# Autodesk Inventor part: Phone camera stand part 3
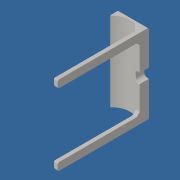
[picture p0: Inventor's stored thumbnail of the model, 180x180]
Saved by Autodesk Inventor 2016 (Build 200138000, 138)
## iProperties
Created: 2016-02
Part Number: Phone camera stand part 3
Material: Generic
Document SubType Name: Modeling
Designer: Miha
Density: 1 g/cm^3
Appearance: Default
Author: Miha
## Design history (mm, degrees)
sketch "Sketch1"
  geometry: L1 (0, 0)-(45, 0); L2 (0, 0)-(45, 0); L3 (45, 0)-(45, -20); L4 (45, 0)-(65, 0); L5 (45, 0)-(45, 20); L6 (45, 0)-(65, 0); L7 (45, -20)-(0, -20); L8 (0, -20)-(0, -24.8); L9 (0, -24.8)-(45, -24.8); L10 (45, -24.8)-(45, -20); L11 (45, 20)-(0, 20); L12 (0, 20)-(0, 24.8); L13 (0, 24.8)-(45, 24.8); L14 (45, 24.8)-(45, 20)
  constraints: 28 end point, 6 horizontal, 4 parallel, 3 equal length, 3 perpendicular, 1 vertical
  dimensions: "d20" = 45 distance of L1.start L1.end; "d21" = 0 distance between parallel lines of L1 L2 (derived); "d22" = 20 distance of L2.end L3.end; "d23" = 90 deg angle of L3 L4 (derived); "d24" = 20 distance of L2.end L5.end; "d25" = 90 deg angle of L6 L5 (derived); "d26" = 45 distance of L9.end L8.end; "d27" = 4.8 distance of L8.end L7.end; "d28" = 45 distance of L12.end L13.end; "d29" = 4.8 distance of L11.end L12.end
extrude "Extrusion1" new body sketch "Sketch1" distance "d30" = 3; taper "d31" = 0 deg
sketch "Sketch2"
  geometry: L1 (3, 4.8)-(3, 0) reference; L2 (3, 0)-(-7, 0); L3 (-7, 0)-(-7, 49.6); L4 (-7, 49.6)-(3, 49.6); L5 (3, 49.6)-(3, 0); 1 further point
  constraints: 8 end point, 2 parallel, 1 horizontal, 1 perpendicular
  dimensions: "d32" = 10 distance of L3.end L4.end; "d33" = 49.6 distance of L2.end L3.end
extrude "Extrusion2" join sketch "Sketch2" distance "d34" = 2; taper "d35" = 0 deg
sketch "Sketch3"
  geometry: L1 (49.6, 2)-(0, 2) reference; L2 (49.6, 0)-(0, 0) reference; L3 (0, 2)-(49.6, 2); L4 (49.6, 2)-(49.6, 0); L5 (49.6, 0)-(0, 0); L6 (0, 0)-(0, 2); 1 further point
  constraints: 8 end point, 2 parallel, 1 horizontal, 1 perpendicular
extrude "Extrusion3" join sketch "Sketch3" distance "d36" = 8.7; taper "d37" = 0 deg
chamfer "Chamfer1" distance "d38" = 3.7; stored, may be unused: second distance "d39" = 2, angle "d40" = 45 deg
sketch "Sketch4"
  geometry: L1 (-3.7, 45)-(0, 41.3) reference; L2 (3, 45)-(-3.7, 45) reference; L3 (-3.7, 45)-(3, 45); L4 (3, 45)-(3, 41.3); L5 (3, 0)-(3, 47) reference; L6 (0, 41.3)-(0, 0) reference; L7 (3, 41.3)-(0, 41.3); L8 (0, 41.3)-(-3.7, 45)
  constraints: 8 end point, 2 collinear, 1 horizontal, 1 point on line
extrude "Extrusion4" join sketch "Sketch4" stored distance "d41" = 8.7; taper "d42" = 0 deg
chamfer "Chamfer2" distance "d43" = 2; stored, may be unused: second distance "d44" = 2, angle "d45" = 45 deg
fillet "Fillet2" dims "d47" = 1.1
sketch "Sketch5"
  geometry: L1 (0, 24.8)-(3, 24.8); L2 (3, 42.8)-(3, 6.8) reference; L3 (0, 24.8)-(0, 21.8); L4 (0.456, 42.803)-(0.456, 6.797) reference; L5 (0, 24.8)-(3, 24.8); L6 (0, 21.8)-(3, 21.8); L7 (3, 21.8)-(3, 27.8); L8 (3, 27.8)-(0, 27.8); L9 (0, 27.8)-(0, 21.8); 4 further points
  constraints: 14 end point, 3 parallel, 2 horizontal, 2 perpendicular, 1 midpoint
  dimensions: "d53" = 3 distance of L1.start L3.end; "d54" = 90 deg angle of L3 L5 (derived); "d55" = 3 distance of L8.end L7.end; "d56" = 6 distance of L7.end L6.end
extrude "Extrusion5" cut sketch "Sketch5" distance "d57" = 8.7; taper "d58" = 0 deg
fillet "Fillet8" dims "d59" = 2
sketch "Sketch7"
  geometry: L1 (0, 0)-(12, 0) reference; L2 (12, 0)-(12, -4); L3 (12, 0)-(16, 0); L4 (5.177, 0)-(12, 0); L5 (12, 0)-(12, -4); A1 r 12.506 centre (2.588, -12.235) between (12, -4) and (5.177, 0); 1 further point
  constraints: 8 end point, 2 perpendicular, 2 point on circle, 1 centre point, 1 collinear, 1 horizontal, 1 point on line, 1 vertical
  dimensions: "d62" = 4 distance of L1.end L2.end; "d63" = 90 deg angle of L2 L3 (derived)
extrude "Extrusion6" join sketch "Sketch7" stored distance "d64" = 8.7; taper "d65" = 0 deg
fillet "Fillet9" dims "d66" = 2
sketch "Sketch8"
  geometry: L1 (0, 25.8)-(-4, 25.8); L2 (-3.114, 49.6)-(-3.114, 0) reference; L3 (0, 25.8)-(4, 25.8); L4 (0, 25.8)-(0, 23.8) reference; L5 (0, 25.8)-(0, 23.8); L6 (0, 23.8)-(-4, 23.8); L7 (-4, 23.8)-(-4, 25.8); A1 r 2 centre (2, 25.8) between (2, 27.8) and (0, 25.8) reference; 1 further point
  constraints: 10 end point, 2 equal length, 2 perpendicular, 1 collinear, 1 horizontal
  dimensions: "d67" = 4 distance of L1.start L1.end; "d68" = 180 deg angle of L1 L3 (derived)
extrude "Extrusion7" join sketch "Sketch8" distance "d69" = 4; taper "d70" = 0 deg
sketch "Sketch10"
  geometry: L1 (0, 4)-(4, 4) reference; L2 (4, 4)-(7, 4); L3 (4, 4)-(7, 4); L4 (7, 4)-(4, 0); L5 (15.7, 0)-(-3, 0) reference; L6 (0, -5.7)-(0, 0) reference; L7 (0, 0)-(2.833, 4); L8 (4, 0)-(4, 4) reference; L9 (4, 0)-(4, 4); 2 further points
  constraints: 10 end point, 2 collinear, 2 horizontal, 2 point on line
  dimensions: "d71" = 3 distance of L1.end L2.end; "d72" = 0 distance between parallel lines of L2 L3 (derived)
extrude "Extrusion8" join sketch "Sketch10" stored distance "d73" = 4; taper "d74" = 0 deg
sketch "Sketch11"
  geometry: L1 (15.7, 0)-(-3, 0) reference; L2 (0, 0)-(3.5, 4); L3 (7, 4)-(0, 4) reference; L4 (3.5, 4)-(0, 4); L5 (0, 0)-(0, 4) reference; L6 (0, 4)-(0, 0); L7 (0, 0)-(3.5, 4); 1 further point
  constraints: 8 end point, 2 collinear, 1 midpoint, 1 perpendicular, 1 point on line
extrude "Extrusion9" cut sketch "Sketch11" distance "d75" = 4; taper "d76" = 0 deg
sketch "Sketch12"
  geometry: L1 (4, 0)-(7, 4) reference; L2 (7, 4)-(0.95, 4); L3 (0.95, 4)-(0.95, 2); L4 (0.95, 2)-(7, 2); L5 (7, 2)-(7, 4); 1 further point
  constraints: 8 end point, 2 parallel, 1 horizontal, 1 perpendicular
  dimensions: "d78" = 2 distance of L3.end L2.end
extrude "Extrusion10" cut sketch "Sketch12" distance "d79" = 4; taper "d80" = 0 deg
fillet "Fillet11" dims "d81" = 2
sketch "Sketch14"
  geometry: L1 (0, 0)-(3, 0) reference; L2 (0, 4.8)-(3, 4.8) reference; L3 (0, 0)-(3, 0); L4 (3, 0)-(3, 4.8); L5 (3, 4.8)-(0, 4.8); L6 (0, 4.8)-(0, 0); L7 (0, 49.6)-(3, 49.6) reference; L8 (0, 42.8)-(0, 49.6) reference; L9 (3, 49.6)-(0, 49.6); L10 (0, 49.6)-(0, 44.8); L11 (0, 44.8)-(3, 44.8); L12 (3, 44.8)-(3, 49.6); 1 further point
  constraints: 16 end point, 4 parallel, 2 horizontal, 2 perpendicular, 1 point on line
extrude "Extrusion11" join sketch "Sketch14" distance "d82" = 10; taper "d83" = 0 deg
fillet "Fillet13" dims "d85" = 1.1
fillet "Fillet15" dims "d87" = 0.3
fillet "Fillet17" dims "d89" = 0.5
fillet "Fillet18" dims "d90" = 0.5
fillet "Fillet19" dims "d91" = 1
fillet "Fillet20" dims "d92" = 0.1
fillet "Fillet21" dims "d93" = 0.3
sketch "Sketch15"
  geometry: L1 (3, 44.8)-(0, 44.8); L2 (0, 44.8)-(0, 49.6); L3 (0, 49.6)-(3, 49.6); L4 (3, 49.6)-(3, 44.8); L5 (3, 0)-(3, 4.8) reference; L6 (0, 3.7)-(0, 1.1) reference; L7 (3, 0)-(0, 0); L8 (0, 0)-(0, 4.8); L9 (0, 4.8)-(3, 4.8); L10 (3, 4.8)-(3, 0); 4 further points
  constraints: 16 end point, 4 parallel, 2 horizontal, 2 perpendicular
extrude "Extrusion12" join sketch "Sketch15" distance "d94" = 16; taper "d95" = 0 deg
fillet "Fillet22" dims "d96" = 1.1
sketch "Sketch16"
  geometry: L1 (-2.548, 56.339)-(5.91, 56.339); L2 (5.91, 56.339)-(5.91, -3.784); L3 (5.91, -3.784)-(-2.548, -3.784); L4 (-2.548, -3.784)-(-2.548, 56.339); 1 further point
  constraints: 8 end point, 2 parallel, 1 horizontal, 1 perpendicular
extrude "Extrusion13" cut sketch "Sketch16" distance "d98" = 16; taper "d99" = 0 deg
fillet "Fillet24" dims "d100" = 1
body "Solid1"
